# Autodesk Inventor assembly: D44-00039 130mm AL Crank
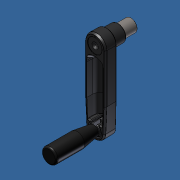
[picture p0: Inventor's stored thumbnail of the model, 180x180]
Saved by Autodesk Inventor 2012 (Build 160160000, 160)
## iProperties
Created: 2013-10
Part Number: D44-00039 130mm AL Crank
Document SubType Name: Assembly
Designer: Admin
Author: Admin
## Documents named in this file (5)
- C:\Andys Backup Data\ANDY'S INVENTOR\INVENTOR LIBRARIES\PARTS LIBRARY\HYDRAULIC VERTICAL ADJUSTMENT\27.9001Telescoping Twin Leg System\SUBCOMPONENTS\Qxx18_crank pump\D44-00039 130mm AL Crank.iam
- C:\Andys Backup Data\ANDY'S INVENTOR\INVENTOR LIBRARIES\PARTS LIBRARY\HYDRAULIC VERTICAL ADJUSTMENT\27.9001Telescoping Twin Leg System\SUBCOMPONENTS\Qxx18_crank pump\665-02106 Crank Body.ipt
- C:\Andys Backup Data\ANDY'S INVENTOR\INVENTOR LIBRARIES\PARTS LIBRARY\HYDRAULIC VERTICAL ADJUSTMENT\27.9001Telescoping Twin Leg System\SUBCOMPONENTS\Qxx18_crank pump\697-00125 M6X16 FLATHEAD CAP SCREW.ipt
- C:\Andys Backup Data\ANDY'S INVENTOR\INVENTOR LIBRARIES\PARTS LIBRARY\HYDRAULIC VERTICAL ADJUSTMENT\27.9001Telescoping Twin Leg System\SUBCOMPONENTS\Qxx18_crank pump\644-01043 FOLDING HANDLE_Open Handle.iam
- C:\Andys Backup Data\ANDY'S INVENTOR\INVENTOR LIBRARIES\PARTS LIBRARY\HYDRAULIC VERTICAL ADJUSTMENT\27.9001Telescoping Twin Leg System\SUBCOMPONENTS\Qxx18_crank pump\665-02107 HEX CRANK ADAPTER.ipt
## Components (4 placed, 4 different names)
1. 665-02106 Crank Body:1
2. 697-00125 M6X16 FLATHEAD CAP SCREW:1
3. 644-01043 FOLDING HANDLE_Open Handle:1 [sub-assembly]
4. 665-02107 HEX CRANK ADAPTER:1
